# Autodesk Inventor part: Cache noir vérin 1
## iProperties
Author: administrateur
Created: 2002-09
Part Number: Cache noir vérin 1
Material: Par défaut
Document SubType Name: Modélisation
Designer: administrateur
Control State: 0
Master: False
Checked Out: False
PropertySet Name: Design Tracking Control
Shininess: 20.0
Angle Display Precision: 2
Document Length Units: 11269
Document Angle Units: 11283
Document Time Units: 11279
Document Mass Units: 11290
Document Length Units Precision: 3
Document Angle Units Precision: 2
Compacted: False
PropertySet Name: _Private Model Information
Density: 0.0
Volumn: 0.0
Area: 0.0
PropertySet Name: Model Information
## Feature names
1. Extrusion1
2. Chanfrein1 [Chamfer]
3. Chanfrein2 [Chamfer]
4. Chanfrein3 [Chamfer]
5. Chanfrein4 [Chamfer]
6. Congé1 [Fillet]
7. Congé2 [Fillet]
